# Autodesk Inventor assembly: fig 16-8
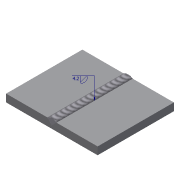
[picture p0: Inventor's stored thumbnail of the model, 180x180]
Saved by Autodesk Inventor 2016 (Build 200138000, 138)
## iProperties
Created: 2004-07
Part Number: fig 16-8
Document SubType Name: Weldment
Designer: CADCIM Technologies
Manufacturer: Standard
Standards Organization: Custom
Author: CADCIM Technologies
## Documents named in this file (2)
- D:\KAVITA\Autodesk Inventor_ 2016 Project_Kavita\Inventor_Part Files\Inventor_2016_Part\c16_Inv_2016\c16_inv_2016_prt\fig 16-8\fig 16-8.iam
- D:\KAVITA\Autodesk Inventor_ 2016 Project_Kavita\Inventor_Part Files\Inventor_2016_Part\c16_Inv_2016\c16_inv_2016_prt\fig 16-8\Plate.ipt
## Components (2 placed, 1 different names)
1. Plate:1 — Mate:1, Flush:1, Flush:2
2. Plate:2 — Mate:1, Flush:1, Flush:2
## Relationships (3: Flush 2, Mate 1)
- Mate:1: Plate:1 ↔ Plate:2
- Flush:1: Plate:1 ↔ Plate:2
- Flush:2: Plate:1 ↔ Plate:2
